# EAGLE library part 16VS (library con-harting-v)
CONNECTOR
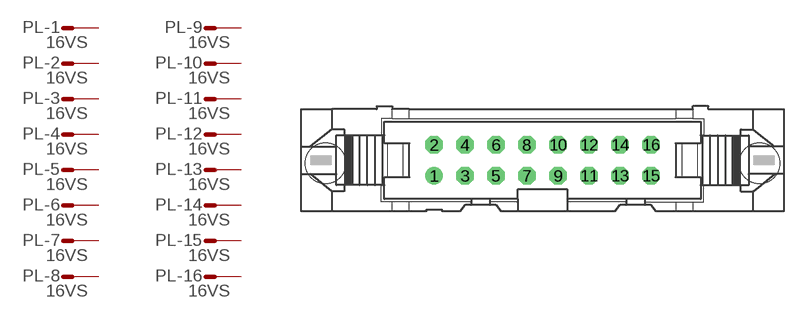
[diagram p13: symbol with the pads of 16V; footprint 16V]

Designator prefix PL; gates -1=M -2=M -3=M -4=M -5=M -6=M -7=M -8=M -9=M -10=M -11=M -12=M -13=M -14=M -15=M -16=M

## 16VS (OC_FARNELL: unknown; OC_NEWARK: unknown)  [16V]
1  -1:S  pas
2  -2:S  pas
3  -3:S  pas
4  -4:S  pas
5  -5:S  pas
6  -6:S  pas
7  -7:S  pas
8  -8:S  pas
9  -9:S  pas
10  -10:S  pas
11  -11:S  pas
12  -12:S  pas
13  -13:S  pas
14  -14:S  pas
15  -15:S  pas
16  -16:S  pas

## Footprint 16V (pad centres in mm)
CONNECTOR
drill 0.914 round: 1 -8.89,-1.27
drill 0.914 octagon: 2 -8.89,1.27; 3 -6.35,-1.27; 4 -6.35,1.27; 5 -3.81,-1.27; 6 -3.81,1.27; 7 -1.27,-1.27; 8 -1.27,1.27; 9 1.27,-1.27; 10 1.27,1.27; 11 3.81,-1.27; 12 3.81,1.27; 13 6.35,-1.27; 14 6.35,1.27; 15 8.89,-1.27; 16 8.89,1.27
hole 3.302 at 17.78,-0.254
hole 3.302 at -17.78,-0.254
